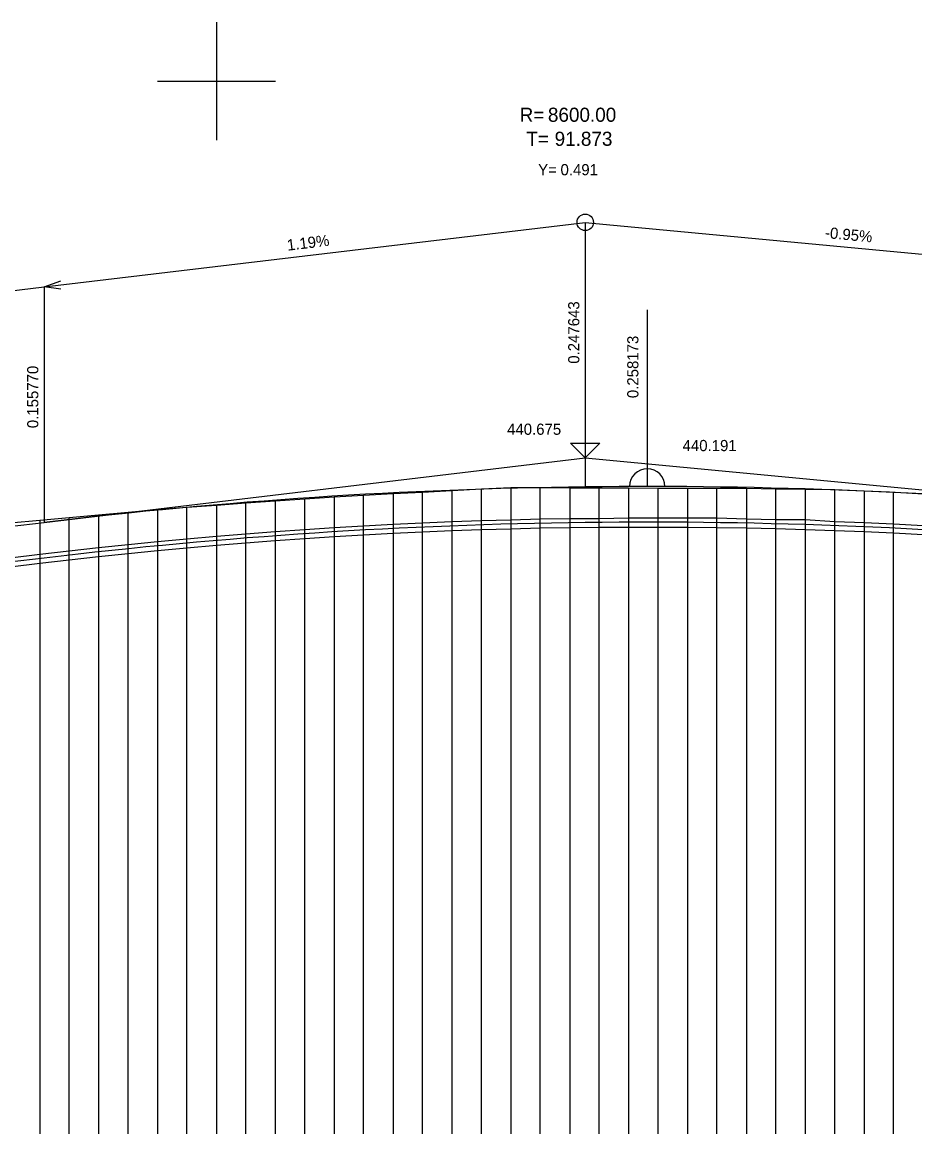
# Model space of a CAD drawing. Extents: x -240 to 1040, y 276 to 593.
# Drawn here: x 157 to 308.6, y 404 to 592.7 of the extents above; entities that cross this region are included whole.
import ezdxf

# ---------------------------------------------------------------- set-up
doc = ezdxf.new("R2010")
doc.units = 0
for name, color, linetype in [('1', 7, 'Continuous'), ('2', 7, 'Continuous'), ('FORMATY', 7, 'Continuous')]:
    doc.layers.add(name, color=color, linetype=linetype)

msp = doc.modelspace()

# ---------------------------------------------------------------- linework, layer by layer
at = {"layer": '1'}
for p, q in [((235, 513.43), (230, 513.17)), ((240, 513.68), (235, 513.43)), ((235, 404), (235, 513.43)), ((240, 513.68), (240, 404)), ((245, 513.66), (240, 513.68)), ((245, 404), (245, 513.66)), ((250, 513.64), (245, 513.66)), ((250, 513.64), (250, 404)), ((255, 513.63), (250, 513.64)), ((255, 404), (255, 513.63)), ((260, 513.61), (255, 513.63)), ((260, 513.61), (260, 404)), ((265, 513.59), (260, 513.61)), ((265, 404), (265, 513.59)), ((270, 513.56), (265, 513.59)), ((275, 513.57), (270, 513.56)), ((270, 513.56), (270, 404)), ((275, 404), (275, 513.57)), ((280, 513.54), (275, 513.57)), ((280, 513.54), (280, 404)), ((285, 513.47), (280, 513.54)), ((285, 404), (285, 513.47)), ((290, 513.39), (285, 513.47)), ((290, 513.39), (290, 404)), ((295, 513.34), (290, 513.39)), ((205, 511.77), (200, 511.41)), ((210, 512.12), (205, 511.77)), ((205, 404), (205, 511.77)), ((215, 512.39), (210, 512.12)), ((210, 512.12), (210, 404)), ((220, 512.65), (215, 512.39)), ((215, 404), (215, 512.39)), ((225, 512.91), (220, 512.65)), ((220, 512.65), (220, 404)), ((230, 513.17), (225, 512.91)), ((225, 404), (225, 512.91)), ((230, 513.17), (230, 404)), ((295, 404), (295, 513.34)), ((300, 513.1), (295, 513.34)), ((300, 513.1), (300, 404)), ((305, 512.87), (300, 513.1)), ((305, 404), (305, 512.87)), ((310, 512.67), (305, 512.87)), ((180, 509.93), (175, 509.48)), ((185, 510.33), (180, 509.93)), ((180, 509.93), (180, 404)), ((190, 510.69), (185, 510.33)), ((185, 404), (185, 510.33)), ((195, 511.05), (190, 510.69)), ((190, 510.69), (190, 404)), ((200, 511.41), (195, 511.05)), ((195, 404), (195, 511.05)), ((200, 511.41), (200, 404)), ((160, 508.13), (155, 507.67)), ((165, 508.59), (160, 508.13)), ((160, 508.13), (160, 404)), ((170, 509.02), (165, 508.59)), ((165, 404), (165, 508.59)), ((175, 509.48), (170, 509.02)), ((170, 509.02), (170, 404)), ((175, 404), (175, 509.48))]:
    msp.add_line(p, q, dxfattribs=at)
at = {"layer": '2'}
for p, q in [((160.77, 547.81), (252.64, 558.75)), ((252.64, 558.75), (252.64, 513.84)), ((252.64, 558.75), (344.52, 550.06)), ((126.49, 543.73), (160.77, 547.81)), ((160.77, 547.81), (163.57, 548.84)), ((160.77, 547.81), (160.77, 507.81)), ((163.57, 547.44), (160.77, 547.81)), ((263.17, 543.91), (263.17, 513.91)), ((252.64, 518.75), (250.14, 521.25)), ((250.14, 521.25), (255.14, 521.25)), ((255.14, 521.25), (252.64, 518.75)), ((160.77, 507.81), (252.64, 518.75)), ((252.64, 518.75), (344.52, 510.06)), ((235.42, 513.46), (232.55, 513.36)), ((238.29, 513.55), (235.42, 513.46)), ((241.16, 513.63), (238.29, 513.55)), ((244.03, 513.69), (241.16, 513.63)), ((246.9, 513.75), (244.03, 513.69)), ((249.77, 513.8), (246.9, 513.75)), ((252.64, 513.84), (249.77, 513.8)), ((255.51, 513.87), (252.64, 513.84)), ((258.39, 513.89), (255.51, 513.87)), ((261.26, 513.9), (258.39, 513.89)), ((266.17, 513.91), (260.17, 513.91)), ((264.13, 513.91), (261.26, 513.9)), ((267, 513.9), (264.13, 513.91)), ((269.87, 513.88), (267, 513.9)), ((272.74, 513.85), (269.87, 513.88)), ((275.61, 513.82), (272.74, 513.85)), ((278.48, 513.77), (275.61, 513.82)), ((281.35, 513.71), (278.48, 513.77)), ((284.22, 513.65), (281.35, 513.71)), ((287.1, 513.57), (284.22, 513.65)), ((289.97, 513.49), (287.1, 513.57)), ((292.84, 513.4), (289.97, 513.49)), ((295.71, 513.29), (292.84, 513.4)), ((200.96, 511.66), (198.09, 511.44)), ((203.84, 511.86), (200.96, 511.66)), ((206.71, 512.05), (203.84, 511.86)), ((209.58, 512.24), (206.71, 512.05)), ((212.45, 512.41), (209.58, 512.24)), ((215.32, 512.58), (212.45, 512.41)), ((218.19, 512.73), (215.32, 512.58)), ((221.06, 512.88), (218.19, 512.73)), ((223.93, 513.01), (221.06, 512.88)), ((226.8, 513.14), (223.93, 513.01)), ((229.67, 513.25), (226.8, 513.14)), ((232.55, 513.36), (229.67, 513.25)), ((298.58, 513.18), (295.71, 513.29)), ((301.45, 513.06), (298.58, 513.18)), ((304.32, 512.92), (301.45, 513.06)), ((307.19, 512.78), (304.32, 512.92)), ((310.06, 512.63), (307.19, 512.78)), ((178, 509.69), (175.12, 509.4)), ((180.87, 509.97), (178, 509.69)), ((183.74, 510.24), (180.87, 509.97)), ((186.61, 510.5), (183.74, 510.24)), ((189.48, 510.75), (186.61, 510.5)), ((192.35, 510.99), (189.48, 510.75)), ((195.22, 511.22), (192.35, 510.99)), ((198.09, 511.44), (195.22, 511.22)), ((126.49, 503.73), (160.77, 507.81)), ((163.64, 508.15), (160.77, 507.81)), ((166.51, 508.47), (163.64, 508.15)), ((169.38, 508.79), (166.51, 508.47)), ((172.25, 509.1), (169.38, 508.79)), ((175.12, 509.4), (172.25, 509.1)), ((244.03, 507.69), (246.9, 507.75)), ((246.9, 507.75), (249.77, 507.8)), ((249.77, 507.8), (252.64, 507.84)), ((252.64, 507.84), (255.51, 507.87)), ((255.51, 507.87), (258.39, 507.89)), ((258.39, 507.89), (261.26, 507.9)), ((261.26, 507.9), (264.13, 507.91)), ((264.13, 507.91), (267, 507.9)), ((267, 507.9), (269.87, 507.88)), ((269.87, 507.88), (272.74, 507.85)), ((272.74, 507.85), (275.61, 507.82)), ((275.61, 507.82), (278.48, 507.77)), ((278.48, 507.77), (281.35, 507.71)), ((281.35, 507.71), (284.22, 507.65)), ((200.96, 505.66), (203.84, 505.86)), ((203.84, 505.86), (206.71, 506.05)), ((206.71, 506.05), (209.58, 506.24)), ((209.58, 506.24), (212.45, 506.41)), ((212.45, 506.41), (215.32, 506.58)), ((215.32, 506.58), (218.19, 506.73)), ((218.19, 506.73), (221.06, 506.88)), ((221.06, 506.88), (223.93, 507.01)), ((223.93, 507.01), (226.8, 507.14)), ((226.8, 507.14), (229.67, 507.25)), ((229.67, 507.25), (232.55, 507.36)), ((232.55, 507.36), (235.42, 507.46)), ((235.42, 507.46), (238.29, 507.55)), ((238.29, 507.55), (241.16, 507.63)), ((241.16, 507.63), (244.03, 507.69)), ((284.22, 507.65), (287.1, 507.57)), ((287.1, 507.57), (289.97, 507.49)), ((289.97, 507.49), (292.84, 507.4)), ((292.84, 507.4), (295.71, 507.29)), ((295.71, 507.29), (298.58, 507.18)), ((298.58, 507.18), (301.45, 507.06)), ((301.45, 507.06), (304.32, 506.92)), ((304.32, 506.92), (307.19, 506.78)), ((307.19, 506.78), (310.06, 506.63)), ((178, 503.69), (180.87, 503.97)), ((180.87, 503.97), (183.74, 504.24)), ((183.74, 504.24), (186.61, 504.5)), ((186.61, 504.5), (189.48, 504.75)), ((189.48, 504.75), (192.35, 504.99)), ((192.35, 504.99), (195.22, 505.22)), ((195.22, 505.22), (198.09, 505.44)), ((198.09, 505.44), (200.96, 505.66)), ((160.77, 501.81), (163.64, 502.15)), ((163.64, 502.15), (166.51, 502.47)), ((166.51, 502.47), (169.38, 502.79)), ((169.38, 502.79), (172.25, 503.1)), ((172.25, 503.1), (175.12, 503.4)), ((175.12, 503.4), (178, 503.69)), ((126.49, 497.73), (160.77, 501.81))]:
    msp.add_line(p, q, dxfattribs=at)
for points in [[(155, 501.8), (160, 502.39), (165, 502.98), (170, 503.53), (175, 504.06), (180, 504.56), (185, 505.03), (190, 505.47), (195, 505.88), (200, 506.26), (205, 506.61), (210, 506.94), (215, 507.23), (220, 507.5), (225, 507.73), (230, 507.94), (235, 508.12), (240, 508.27), (245, 508.39), (250, 508.48), (255, 508.48), (260, 508.58), (265, 508.58), (270, 508.58), (275, 508.58), (280, 508.42), (285, 508.3), (290, 508.3), (295, 507.99), (300, 507.79), (305, 507.56), (310, 507.31)], [(155, 500.26), (160, 500.86), (165, 501.44), (170, 502), (175, 502.53), (180, 503.03), (185, 503.5), (190, 503.93), (195, 504.35), (200, 504.73), (205, 505.08), (210, 505.4), (215, 505.7), (220, 505.96), (225, 506.2), (230, 506.41), (235, 506.59), (240, 506.74), (245, 506.86), (250, 506.95), (255, 507.01), (260, 507.01), (265, 507.01), (270, 507.01), (275, 506.97), (280, 506.88), (285, 506.77), (290, 506.63), (295, 506.46), (300, 506.26), (305, 506.03), (310, 505.77)]]:
    msp.add_lwpolyline(points, dxfattribs=at)
msp.add_circle((252.64, 558.75), 1.4, dxfattribs=at)
msp.add_arc((263.17, 513.91), 3, 0, 180, dxfattribs=at)
at = {"layer": 'FORMATY'}
for p, q in [((190.02, 592.74), (190.02, 572.74)), ((190.02, 592.74), (190.02, 572.74)), ((190.02, 592.74), (190.02, 572.74)), ((190.02, 592.74), (190.02, 572.74)), ((190.02, 592.74), (190.02, 572.74)), ((190.02, 592.74), (190.02, 572.74)), ((180.02, 582.74), (200.02, 582.74)), ((180.02, 582.74), (200.02, 582.74)), ((180.02, 582.74), (200.02, 582.74)), ((180.02, 582.74), (200.02, 582.74)), ((180.02, 582.74), (200.02, 582.74)), ((180.02, 582.74), (200.02, 582.74))]:
    msp.add_line(p, q, dxfattribs=at)

# ---------------------------------------------------------------- texts
at = {"layer": '2'}
for s, height, p in [('R=', 2.4, (241.5, 575.83)), ('8600.00', 2.4, (246.3, 575.83)), ('T=', 2.4, (242.64, 571.75)), ('91.873', 2.4, (247.44, 571.75)), ('Y=', 1.9, (244.64, 566.75)), ('0.491', 1.9, (248.44, 566.75)), ('440.675', 1.9, (239.37, 522.68)), ('440.191', 1.9, (269.17, 519.91))]:
    msp.add_text(s, height=height, dxfattribs=at).set_placement(p)
for s, rotation, p in [(' -0.95%', 354.5967, (292.58, 556.17)), ('  1.19%', 6.7905, (200.71, 553.77)), ('0.247643', 90, (251.64, 534.75)), ('0.258173', 90, (261.67, 528.91)), ('0.155770', 90, (159.77, 523.81))]:
    msp.add_text(s, height=1.9, rotation=rotation, dxfattribs=at).set_placement(p)

doc.saveas('drawing.dxf')
